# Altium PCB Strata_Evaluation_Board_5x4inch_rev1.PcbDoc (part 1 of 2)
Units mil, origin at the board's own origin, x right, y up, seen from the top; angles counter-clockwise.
Board outline 5000 x 4000 mil, 2 copper layers (Top Layer, Bottom Layer); 99 components, 40 nets, 363 pads, 393 vias.
Unrouted connection lines stored in the file: 5.
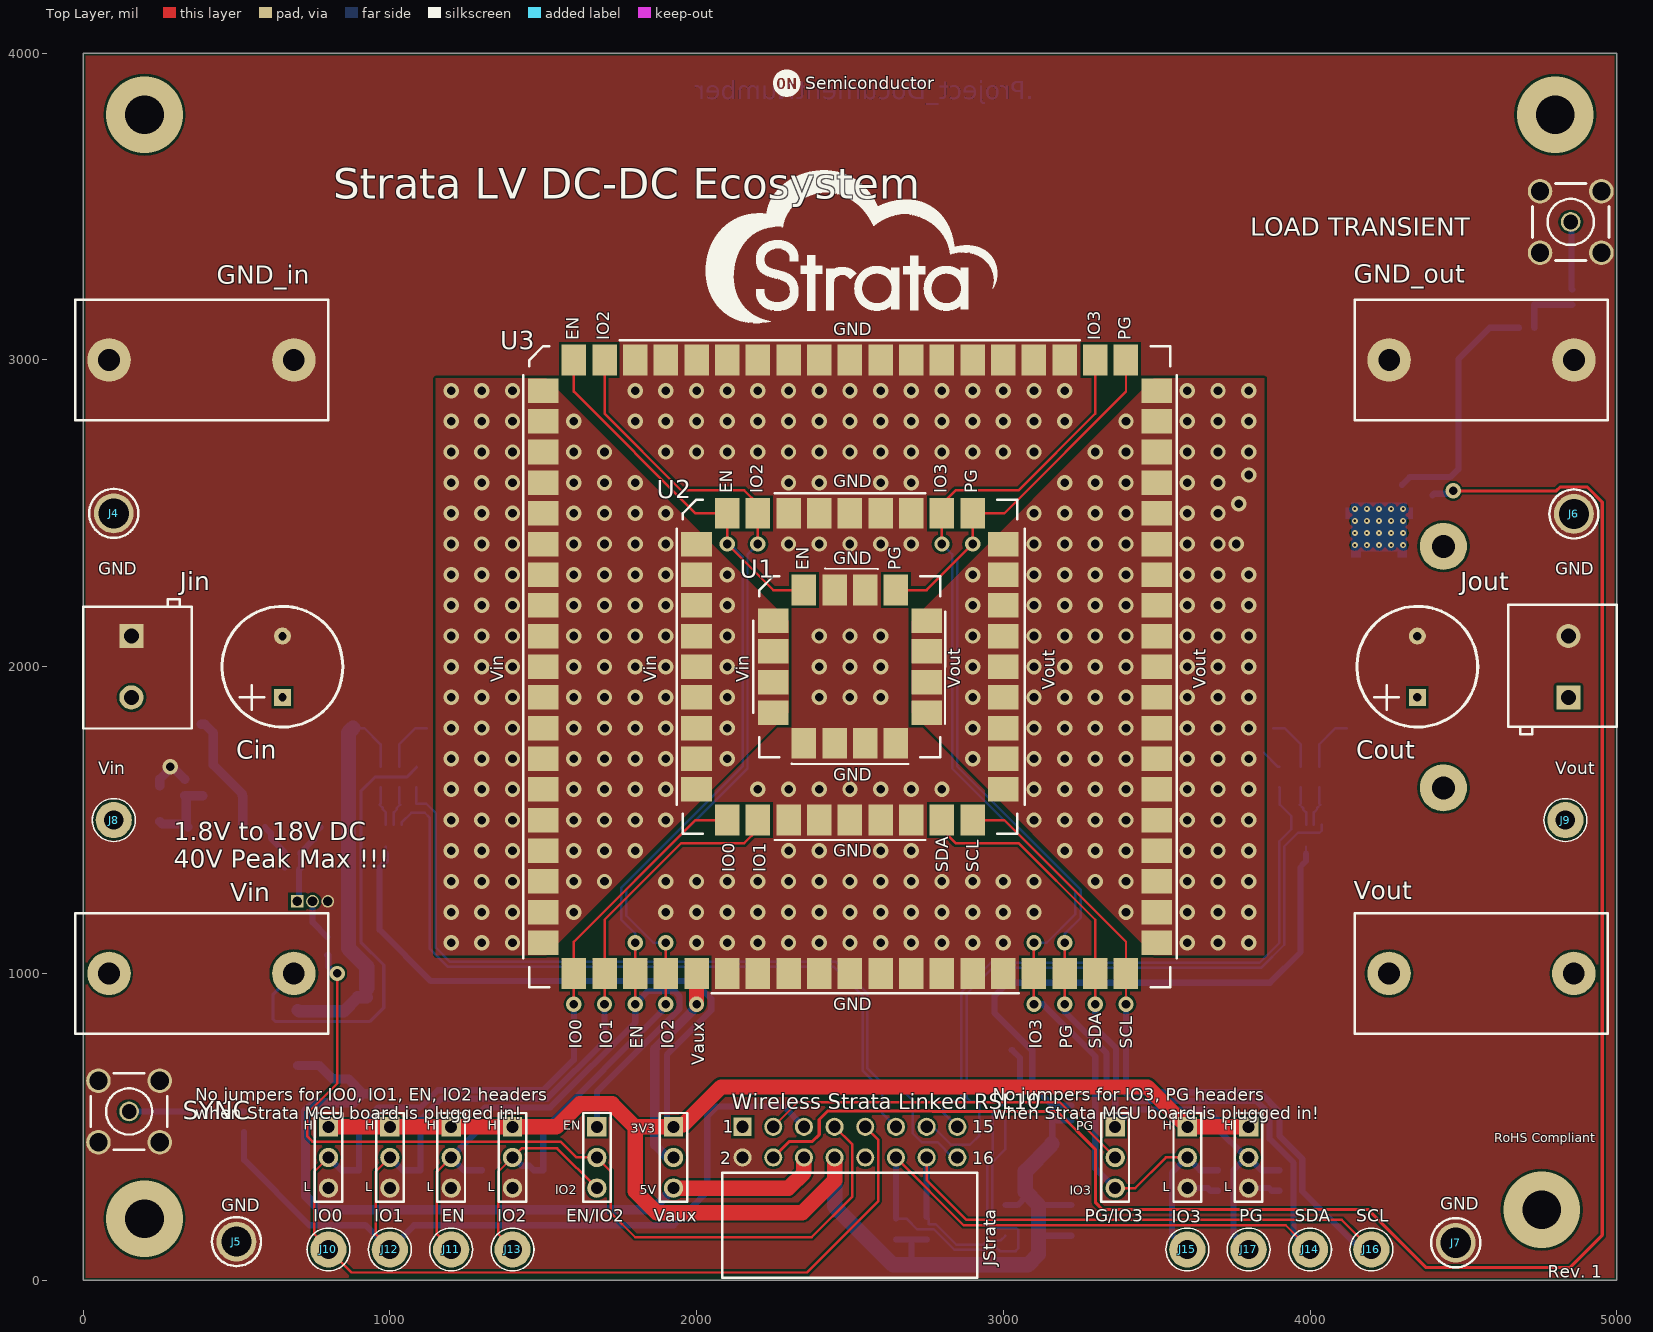
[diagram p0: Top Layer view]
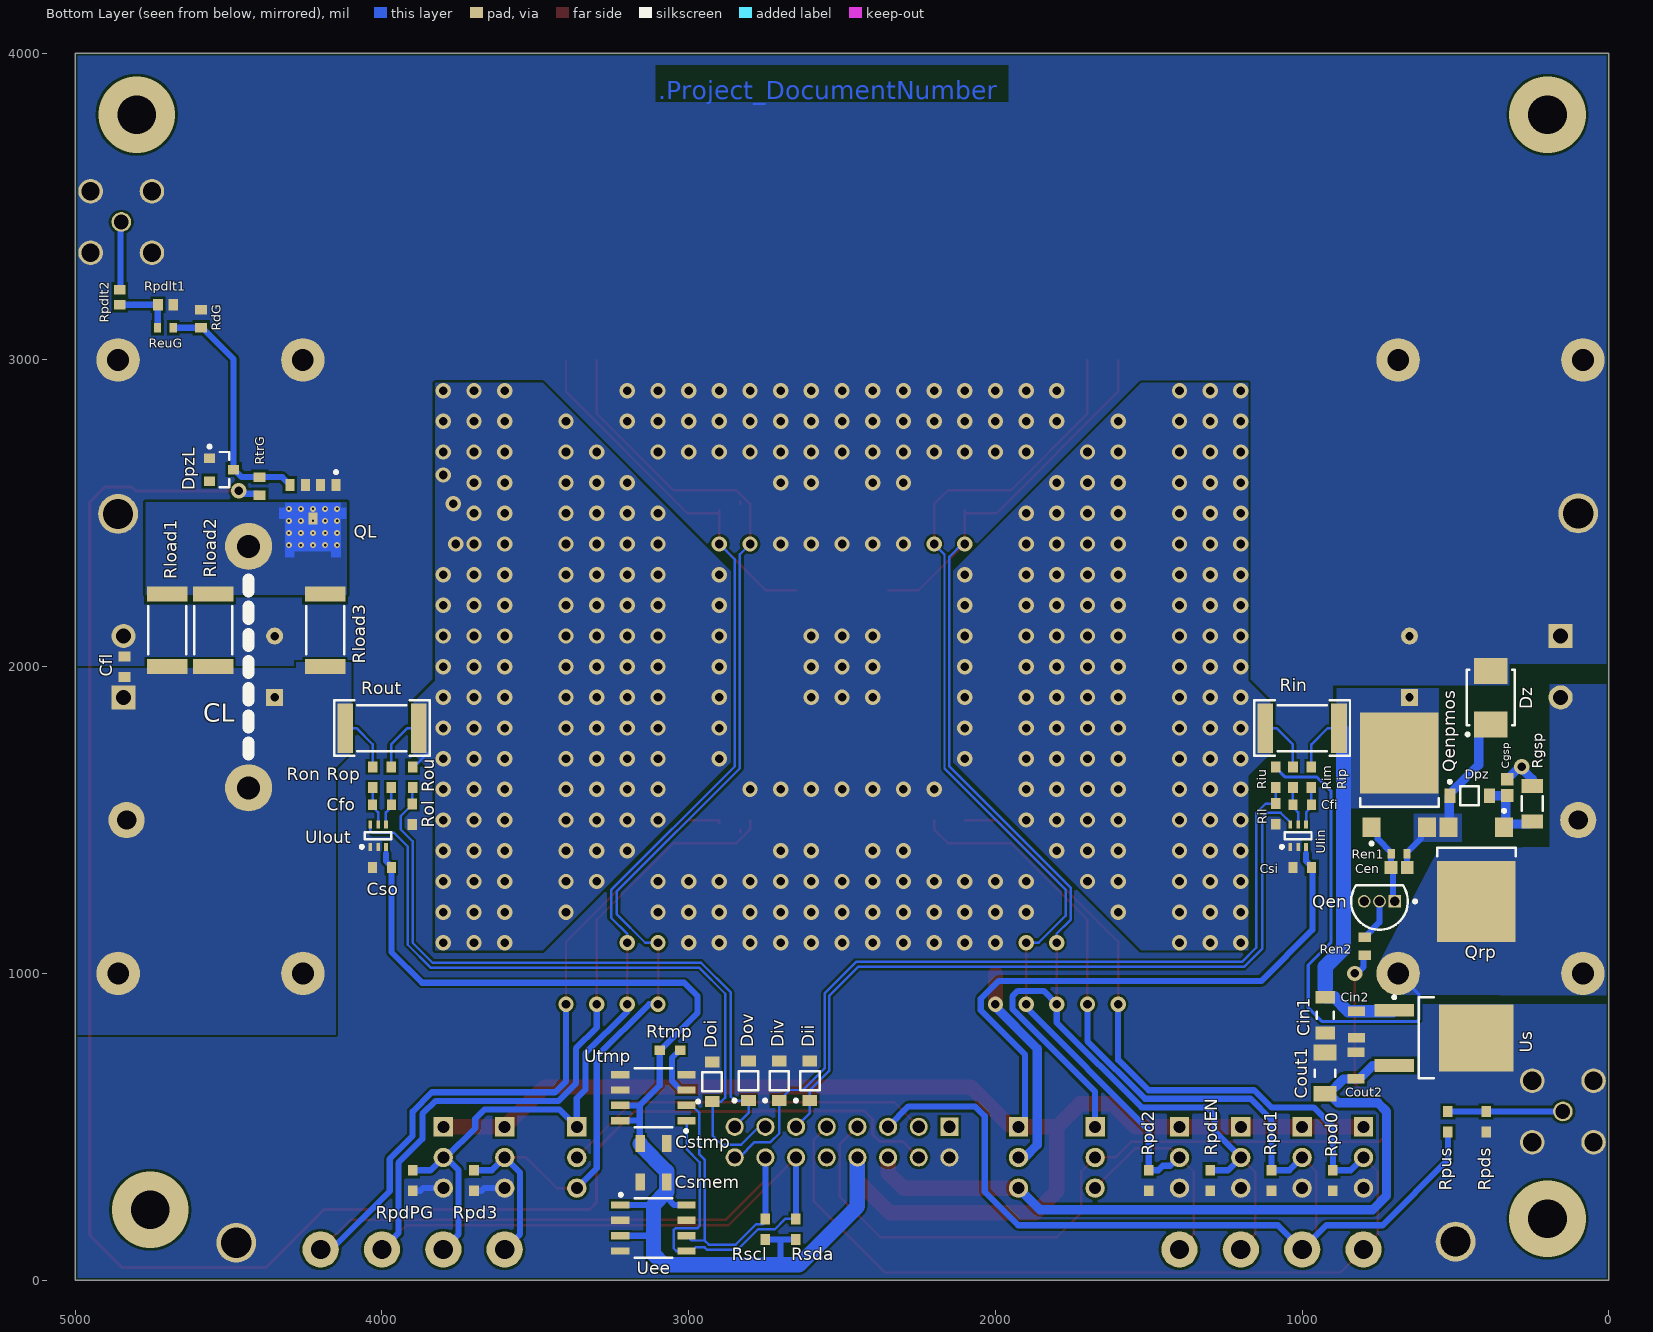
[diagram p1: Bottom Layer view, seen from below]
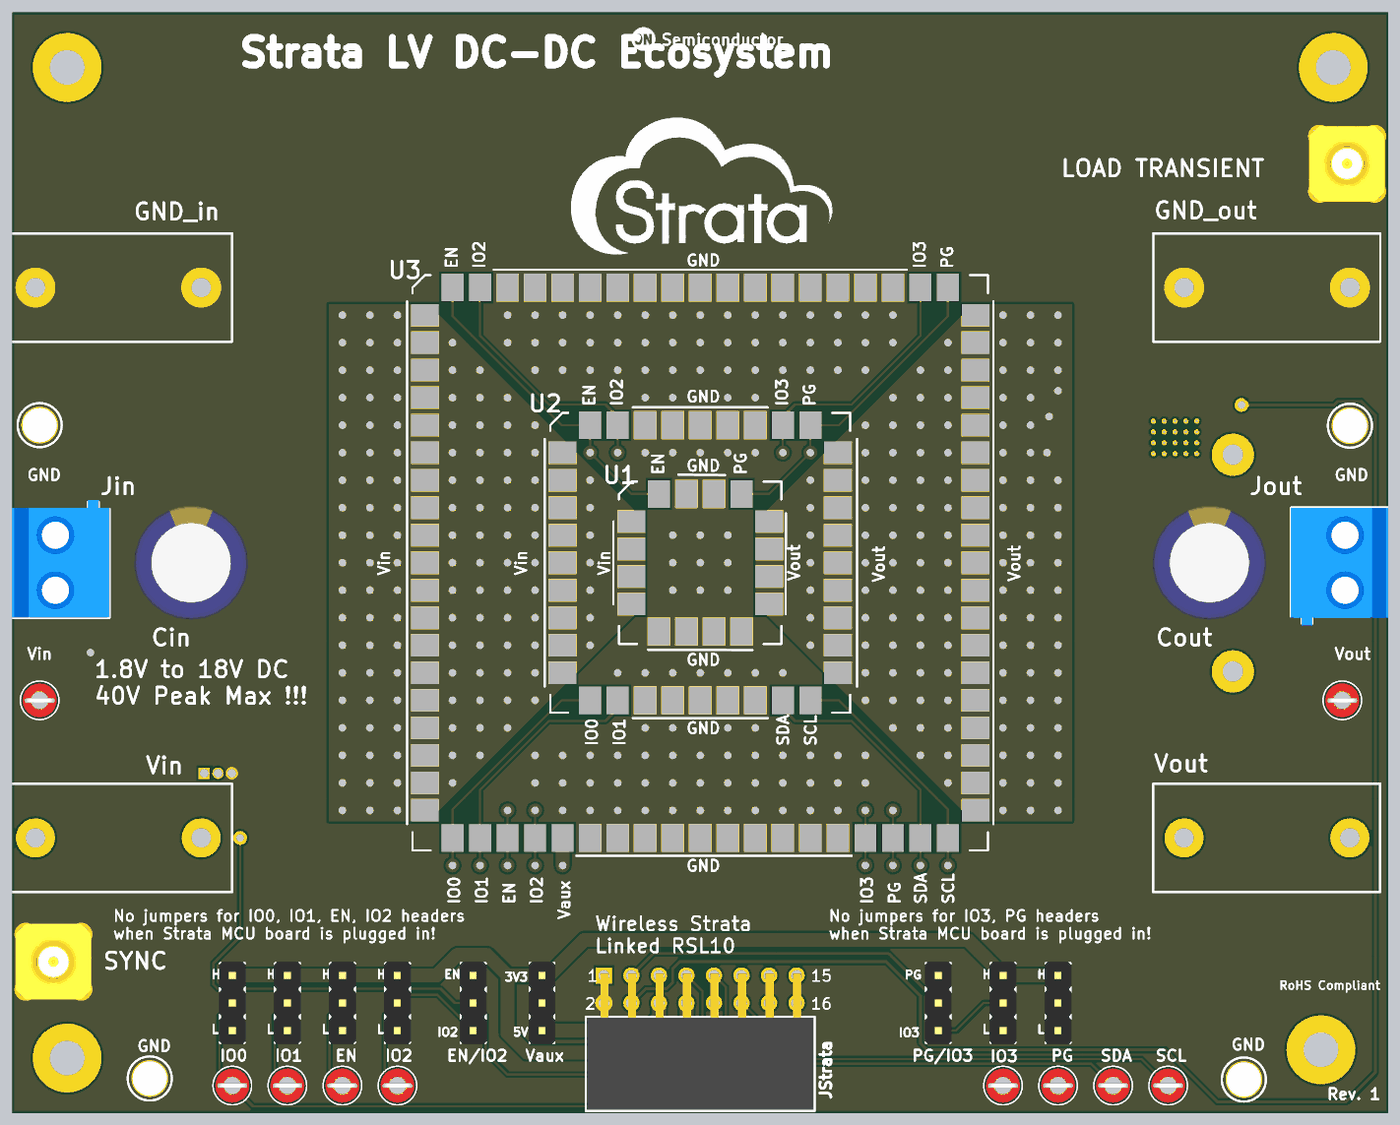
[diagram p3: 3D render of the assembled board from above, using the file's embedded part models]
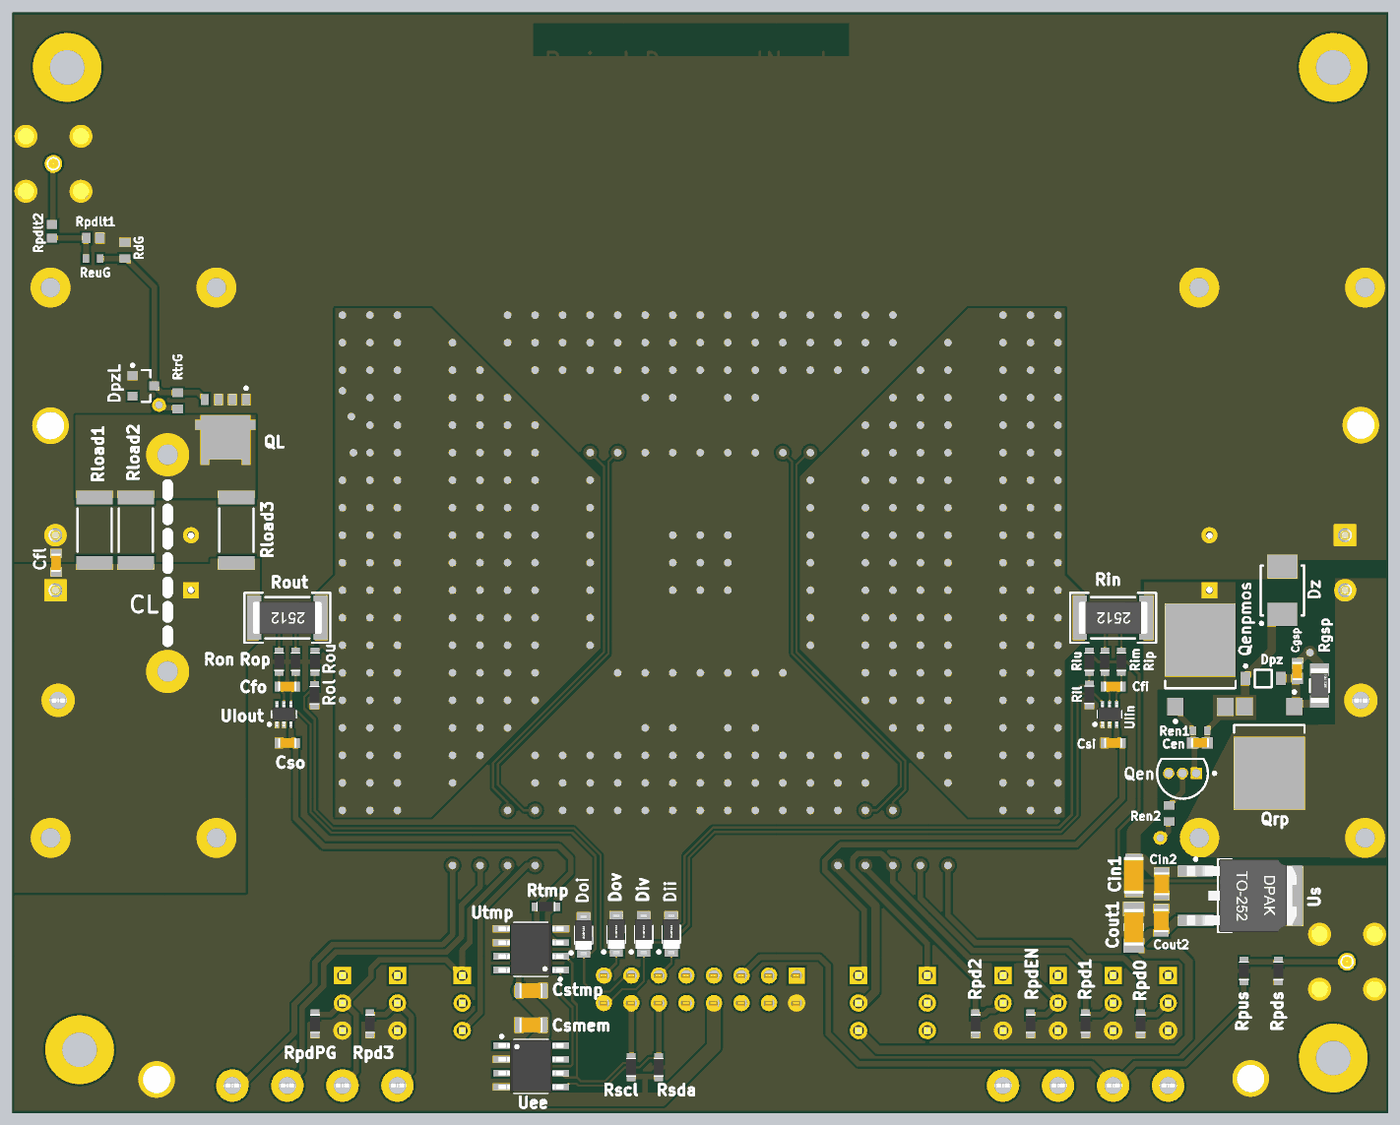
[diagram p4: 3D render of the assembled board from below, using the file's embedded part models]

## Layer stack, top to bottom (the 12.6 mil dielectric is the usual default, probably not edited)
Top Solder: solder mask 0.4, Solder Resist, Dk 3.5
Top Layer: signal copper 1.4
Dielectric 1: dielectric 12.6, FR-4, Dk 4.8
Bottom Layer: signal copper 1.4
Bottom Solder: solder mask 0.4, Solder Resist, Dk 3.5

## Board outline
0,0 5000,0 5000,4000 0,4000

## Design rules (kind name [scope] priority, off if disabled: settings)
BoardOutlineClearance BoardOutlineClearance_TOP [OnLayer('Top Layer')] p1: gap=8 ignorepadtopadclearanceinfootprint=FALSE
BoardOutlineClearance BoardOutlineClearance_BOTTOM [OnLayer('Bottom Layer')] p2: gap=8 ignorepadtopadclearanceinfootprint=FALSE
Clearance [All] p1: gap=8 ignorepadtopadclearanceinfootprint=FALSE
ComponentClearance [All] p1: gap=-10000 collisioncheckmode=3 verticalgap=10 showdistances=FALSE
DiffPairsRouting [All] p1: maxlimit=10 minlimit=6 mostfreqgap=10 toplayer_minwidth=6 toplayer_maxwidth=20 toplayer_prefwidth=10 bottomlayer_minwidth=6 bottomlayer_maxwidth=20 bottomlayer_prefwidth=10 maxuncoupledlength=500
HoleSize [All] p1: absolutevalues=TRUE maxlimit=400 minlimit=8 maxpercent=80.000 minpercent=20.000
MinimumSolderMaskSliver [All] p1: minsoldermaskwidth=1.57
PlaneClearance [All] p1: clearance=6
PolygonConnect Polygon_Direct [All] p1: connectstyle=Direct reliefconductorwidth=10 reliefentries=4 polygonreliefangle="90 Angle" airgapwidth=10
PolygonConnect PolygonConnect_85 [All vs IsNamedPolygon('GND_L01_P2321')] p2: connectstyle=Direct reliefconductorwidth=10 reliefentries=4 polygonreliefangle="90 Angle" airgapwidth=10
PolygonConnect PolygonConnect_84 [All vs IsNamedPolygon('GND_L03_P1821')] p3: connectstyle=Direct reliefconductorwidth=10 reliefentries=4 polygonreliefangle="90 Angle" airgapwidth=10
PolygonConnect PolygonConnect_83 [All vs IsNamedPolygon('VOUTMP_L05_P1813')] p4: connectstyle=Direct reliefconductorwidth=10 reliefentries=4 polygonreliefangle="90 Angle" airgapwidth=10
PolygonConnect PolygonConnect_82 [All vs IsNamedPolygon('VOUTMP_L04_P1815')] p5: connectstyle=Direct reliefconductorwidth=10 reliefentries=4 polygonreliefangle="90 Angle" airgapwidth=10
PolygonConnect PolygonConnect_81 [All vs IsNamedPolygon('GND_L06_P2169')] p6: connectstyle=Direct reliefconductorwidth=10 reliefentries=4 polygonreliefangle="90 Angle" airgapwidth=10
PolygonConnect PolygonConnect_80 [All vs IsNamedPolygon('GND_L06_P2377')] p7: connectstyle=Direct reliefconductorwidth=10 reliefentries=4 polygonreliefangle="90 Angle" airgapwidth=10
PolygonConnect PolygonConnect_79 [All vs IsNamedPolygon('VOUTMP_L04_P1803')] p8: connectstyle=Direct reliefconductorwidth=10 reliefentries=4 polygonreliefangle="90 Angle" airgapwidth=10
PolygonConnect PolygonConnect_78 [All vs IsNamedPolygon('VCC_DUT_L04_P1801')] p9: connectstyle=Direct reliefconductorwidth=10 reliefentries=4 polygonreliefangle="90 Angle" airgapwidth=10
PolygonConnect PolygonConnect_77 [All vs IsNamedPolygon('GND_L06_P1795')] p10: thpad.connectstyle=Relief thpad.reliefconductorwidth=10 thpad.reliefentries=4 thpad.polygonreliefangle="90 Angle" thpad.airgapwidth=10 smdpad.connectstyle=Direct smdpad.reliefconductorwidth=10 smdpad.reliefentries=4 smdpad.polygonreliefangle="90 Angle" smdpad.airgapwidth=10 via.connectstyle=Direct via.reliefconductorwidth=10 via.reliefentries=4 via.polygonreliefangle="90 Angle" via.airgapwidth=10
PolygonConnect PolygonConnect_76 [All vs IsNamedPolygon('GND_L02_P1793')] p11: connectstyle=Direct reliefconductorwidth=10 reliefentries=4 polygonreliefangle="90 Angle" airgapwidth=10
PolygonConnect PolygonConnect_75 [All vs IsNamedPolygon('GND_L03_P1791')] p12: thpad.connectstyle=Relief thpad.reliefconductorwidth=10 thpad.reliefentries=4 thpad.polygonreliefangle="90 Angle" thpad.airgapwidth=10 smdpad.connectstyle=Direct smdpad.reliefconductorwidth=10 smdpad.reliefentries=4 smdpad.polygonreliefangle="90 Angle" smdpad.airgapwidth=10 via.connectstyle=Direct via.reliefconductorwidth=10 via.reliefentries=4 via.polygonreliefangle="90 Angle" via.airgapwidth=10
PolygonConnect PolygonConnect_74 [All vs IsNamedPolygon('NETQLMPB_5_L06_P1787')] p13: thpad.connectstyle=Relief thpad.reliefconductorwidth=10 thpad.reliefentries=4 thpad.polygonreliefangle="90 Angle" thpad.airgapwidth=10 smdpad.connectstyle=Direct smdpad.reliefconductorwidth=10 smdpad.reliefentries=4 smdpad.polygonreliefangle="90 Angle" smdpad.airgapwidth=10 via.connectstyle=Direct via.reliefconductorwidth=10 via.reliefentries=4 via.polygonreliefangle="90 Angle" via.airgapwidth=10
PolygonConnect PolygonConnect_73 [All vs IsNamedPolygon('NETQLMPA_5_L06_P1789')] p14: thpad.connectstyle=Relief thpad.reliefconductorwidth=10 thpad.reliefentries=4 thpad.polygonreliefangle="90 Angle" thpad.airgapwidth=10 smdpad.connectstyle=Direct smdpad.reliefconductorwidth=10 smdpad.reliefentries=4 smdpad.polygonreliefangle="90 Angle" smdpad.airgapwidth=10 via.connectstyle=Direct via.reliefconductorwidth=10 via.reliefentries=4 via.polygonreliefangle="90 Angle" via.airgapwidth=10
PolygonConnect PolygonConnect_72 [All vs IsNamedPolygon('NETQLMPC_5_L06_P1738')] p15: thpad.connectstyle=Relief thpad.reliefconductorwidth=10 thpad.reliefentries=4 thpad.polygonreliefangle="90 Angle" thpad.airgapwidth=10 smdpad.connectstyle=Direct smdpad.reliefconductorwidth=10 smdpad.reliefentries=4 smdpad.polygonreliefangle="90 Angle" smdpad.airgapwidth=10 via.connectstyle=Direct via.reliefconductorwidth=10 via.reliefentries=4 via.polygonreliefangle="90 Angle" via.airgapwidth=10
PolygonConnect PolygonConnect_71 [All vs IsNamedPolygon('NETQL12_5_L06_P1740')] p16: thpad.connectstyle=Relief thpad.reliefconductorwidth=10 thpad.reliefentries=4 thpad.polygonreliefangle="90 Angle" thpad.airgapwidth=10 smdpad.connectstyle=Direct smdpad.reliefconductorwidth=10 smdpad.reliefentries=4 smdpad.polygonreliefangle="90 Angle" smdpad.airgapwidth=10 via.connectstyle=Direct via.reliefconductorwidth=10 via.reliefentries=4 via.polygonreliefangle="90 Angle" via.airgapwidth=10
PolygonConnect PolygonConnect_70 [All vs IsNamedPolygon('NETQL12_5_L06_P1740')] p17: thpad.connectstyle=Relief thpad.reliefconductorwidth=10 thpad.reliefentries=4 thpad.polygonreliefangle="90 Angle" thpad.airgapwidth=10 smdpad.connectstyle=Direct smdpad.reliefconductorwidth=10 smdpad.reliefentries=4 smdpad.polygonreliefangle="90 Angle" smdpad.airgapwidth=10 via.connectstyle=Direct via.reliefconductorwidth=10 via.reliefentries=4 via.polygonreliefangle="90 Angle" via.airgapwidth=10
PolygonConnect PolygonConnect_69 [All vs IsNamedPolygon('NETQLMPD_5_L06_P1736')] p18: thpad.connectstyle=Relief thpad.reliefconductorwidth=10 thpad.reliefentries=4 thpad.polygonreliefangle="90 Angle" thpad.airgapwidth=10 smdpad.connectstyle=Direct smdpad.reliefconductorwidth=10 smdpad.reliefentries=4 smdpad.polygonreliefangle="90 Angle" smdpad.airgapwidth=10 via.connectstyle=Direct via.reliefconductorwidth=10 via.reliefentries=4 via.polygonreliefangle="90 Angle" via.airgapwidth=10
PolygonConnect PolygonConnect_68 [All vs IsNamedPolygon('NETQLMPA_5_L06_P1722')] p19: thpad.connectstyle=Relief thpad.reliefconductorwidth=10 thpad.reliefentries=4 thpad.polygonreliefangle="90 Angle" thpad.airgapwidth=10 smdpad.connectstyle=Direct smdpad.reliefconductorwidth=10 smdpad.reliefentries=4 smdpad.polygonreliefangle="90 Angle" smdpad.airgapwidth=10 via.connectstyle=Direct via.reliefconductorwidth=10 via.reliefentries=4 via.polygonreliefangle="90 Angle" via.airgapwidth=10
PolygonConnect PolygonConnect_67 [All vs IsNamedPolygon('GND_L03_P1716')] p20: connectstyle=Direct reliefconductorwidth=10 reliefentries=4 polygonreliefangle="90 Angle" airgapwidth=10
PolygonConnect PolygonConnect_66 [All vs IsNamedPolygon('GND_L03_P1716')] p21: thpad.connectstyle=Relief thpad.reliefconductorwidth=10 thpad.reliefentries=4 thpad.polygonreliefangle="90 Angle" thpad.airgapwidth=10 smdpad.connectstyle=Relief smdpad.reliefconductorwidth=10 smdpad.reliefentries=4 smdpad.polygonreliefangle="90 Angle" smdpad.airgapwidth=10 via.connectstyle=Direct via.reliefconductorwidth=10 via.reliefentries=4 via.polygonreliefangle="90 Angle" via.airgapwidth=10
PolygonConnect PolygonConnect_65 [All vs IsNamedPolygon('GND_L03_P1716')] p22: thpad.connectstyle=Direct thpad.reliefconductorwidth=10 thpad.reliefentries=4 thpad.polygonreliefangle="90 Angle" thpad.airgapwidth=10 smdpad.connectstyle=Relief smdpad.reliefconductorwidth=10 smdpad.reliefentries=4 smdpad.polygonreliefangle="90 Angle" smdpad.airgapwidth=10 via.connectstyle=Relief via.reliefconductorwidth=10 via.reliefentries=4 via.polygonreliefangle="90 Angle" via.airgapwidth=10
PolygonConnect PolygonConnect_64 [All vs IsNamedPolygon('GND_L03_P1716')] p23: connectstyle=Relief reliefconductorwidth=10 reliefentries=4 polygonreliefangle="90 Angle" airgapwidth=10
PolygonConnect PolygonConnect_63 [All vs IsNamedPolygon('GND_L04_P1728')] p24: connectstyle=Direct reliefconductorwidth=10 reliefentries=4 polygonreliefangle="90 Angle" airgapwidth=10
PolygonConnect PolygonConnect_62 [All vs IsNamedPolygon('G11_L04_P1730')] p25: thpad.connectstyle=Relief thpad.reliefconductorwidth=10 thpad.reliefentries=4 thpad.polygonreliefangle="90 Angle" thpad.airgapwidth=10 smdpad.connectstyle=Direct smdpad.reliefconductorwidth=10 smdpad.reliefentries=4 smdpad.polygonreliefangle="90 Angle" smdpad.airgapwidth=10 via.connectstyle=Direct via.reliefconductorwidth=10 via.reliefentries=4 via.polygonreliefangle="90 Angle" via.airgapwidth=10
PolygonConnect PolygonConnect_61 [All vs IsNamedPolygon('NETQL11_5_L04_P1732')] p26: thpad.connectstyle=Relief thpad.reliefconductorwidth=10 thpad.reliefentries=4 thpad.polygonreliefangle="90 Angle" thpad.airgapwidth=10 smdpad.connectstyle=Direct smdpad.reliefconductorwidth=10 smdpad.reliefentries=4 smdpad.polygonreliefangle="90 Angle" smdpad.airgapwidth=10 via.connectstyle=Direct via.reliefconductorwidth=10 via.reliefentries=4 via.polygonreliefangle="90 Angle" via.airgapwidth=10
PolygonConnect PolygonConnect_60 [All vs IsNamedPolygon('GND_L04_P1718')] p27: connectstyle=Direct reliefconductorwidth=10 reliefentries=4 polygonreliefangle="90 Angle" airgapwidth=10
PolygonConnect PolygonConnect_59 [All vs IsNamedPolygon('G12_L04_P1716')] p28: thpad.connectstyle=Relief thpad.reliefconductorwidth=10 thpad.reliefentries=4 thpad.polygonreliefangle="90 Angle" thpad.airgapwidth=10 smdpad.connectstyle=Direct smdpad.reliefconductorwidth=10 smdpad.reliefentries=4 smdpad.polygonreliefangle="90 Angle" smdpad.airgapwidth=10 via.connectstyle=Direct via.reliefconductorwidth=10 via.reliefentries=4 via.polygonreliefangle="90 Angle" via.airgapwidth=10
PolygonConnect PolygonConnect_58 [All vs IsNamedPolygon('NETQL12_5_L04_P1712')] p29: connectstyle=Direct reliefconductorwidth=10 reliefentries=4 polygonreliefangle="90 Angle" airgapwidth=10
PolygonConnect PolygonConnect_57 [All vs IsNamedPolygon('VOUT111_L01_P1710')] p30: thpad.connectstyle=Direct thpad.reliefconductorwidth=10 thpad.reliefentries=4 thpad.polygonreliefangle="90 Angle" thpad.airgapwidth=10 smdpad.connectstyle=Relief smdpad.reliefconductorwidth=10 smdpad.reliefentries=4 smdpad.polygonreliefangle="90 Angle" smdpad.airgapwidth=10 via.connectstyle=Direct via.reliefconductorwidth=10 via.reliefentries=4 via.polygonreliefangle="90 Angle" via.airgapwidth=10
PolygonConnect PolygonConnect_56 [All vs IsNamedPolygon('VCC_DUT_L06_P1734')] p31: connectstyle=Direct reliefconductorwidth=10 reliefentries=4 polygonreliefangle="90 Angle" airgapwidth=10
PolygonConnect PolygonConnect_55 [All vs IsNamedPolygon('NETC5_1_L01_P1688')] p32: thpad.connectstyle=Relief thpad.reliefconductorwidth=10 thpad.reliefentries=4 thpad.polygonreliefangle="90 Angle" thpad.airgapwidth=10 smdpad.connectstyle=Direct smdpad.reliefconductorwidth=10 smdpad.reliefentries=4 smdpad.polygonreliefangle="90 Angle" smdpad.airgapwidth=10 via.connectstyle=Direct via.reliefconductorwidth=10 via.reliefentries=4 via.polygonreliefangle="90 Angle" via.airgapwidth=10
PolygonConnect PolygonConnect_54 [All vs IsNamedPolygon('GND_L01_P1700')] p33: thpad.connectstyle=Relief thpad.reliefconductorwidth=10 thpad.reliefentries=4 thpad.polygonreliefangle="90 Angle" thpad.airgapwidth=10 smdpad.connectstyle=Direct smdpad.reliefconductorwidth=10 smdpad.reliefentries=4 smdpad.polygonreliefangle="90 Angle" smdpad.airgapwidth=10 via.connectstyle=Direct via.reliefconductorwidth=10 via.reliefentries=4 via.polygonreliefangle="90 Angle" via.airgapwidth=10
PolygonConnect PolygonConnect_53 [All vs IsNamedPolygon('GND_L01_P1608')] p34: thpad.connectstyle=Relief thpad.reliefconductorwidth=10 thpad.reliefentries=4 thpad.polygonreliefangle="90 Angle" thpad.airgapwidth=10 smdpad.connectstyle=Direct smdpad.reliefconductorwidth=10 smdpad.reliefentries=4 smdpad.polygonreliefangle="90 Angle" smdpad.airgapwidth=10 via.connectstyle=Direct via.reliefconductorwidth=10 via.reliefentries=4 via.polygonreliefangle="90 Angle" via.airgapwidth=10
PolygonConnect PolygonConnect_52 [All vs IsNamedPolygon('VREF_L01_P1696')] p35: connectstyle=Direct reliefconductorwidth=10 reliefentries=4 polygonreliefangle="90 Angle" airgapwidth=10
PolygonConnect PolygonConnect_51 [All vs IsNamedPolygon('VREF_L01_P1696')] p36: thpad.connectstyle=Relief thpad.reliefconductorwidth=10 thpad.reliefentries=4 thpad.polygonreliefangle="90 Angle" thpad.airgapwidth=10 smdpad.connectstyle=Direct smdpad.reliefconductorwidth=10 smdpad.reliefentries=4 smdpad.polygonreliefangle="90 Angle" smdpad.airgapwidth=10 via.connectstyle=Direct via.reliefconductorwidth=10 via.reliefentries=4 via.polygonreliefangle="90 Angle" via.airgapwidth=10
PolygonConnect PolygonConnect_50 [All vs IsNamedPolygon('NETC2_1_L01_P1698')] p37: thpad.connectstyle=Relief thpad.reliefconductorwidth=10 thpad.reliefentries=4 thpad.polygonreliefangle="90 Angle" thpad.airgapwidth=10 smdpad.connectstyle=Direct smdpad.reliefconductorwidth=10 smdpad.reliefentries=4 smdpad.polygonreliefangle="90 Angle" smdpad.airgapwidth=10 via.connectstyle=Direct via.reliefconductorwidth=10 via.reliefentries=4 via.polygonreliefangle="90 Angle" via.airgapwidth=10
PolygonConnect PolygonConnect_49 [All vs IsNamedPolygon('NETC1_1_L01_P1694')] p38: thpad.connectstyle=Relief thpad.reliefconductorwidth=10 thpad.reliefentries=4 thpad.polygonreliefangle="90 Angle" thpad.airgapwidth=10 smdpad.connectstyle=Direct smdpad.reliefconductorwidth=10 smdpad.reliefentries=4 smdpad.polygonreliefangle="90 Angle" smdpad.airgapwidth=10 via.connectstyle=Direct via.reliefconductorwidth=10 via.reliefentries=4 via.polygonreliefangle="90 Angle" via.airgapwidth=10
PolygonConnect PolygonConnect_48 [All vs IsNamedPolygon('VID_BUFF_L01_P1690')] p39: thpad.connectstyle=Relief thpad.reliefconductorwidth=10 thpad.reliefentries=4 thpad.polygonreliefangle="90 Angle" thpad.airgapwidth=10 smdpad.connectstyle=Direct smdpad.reliefconductorwidth=10 smdpad.reliefentries=4 smdpad.polygonreliefangle="90 Angle" smdpad.airgapwidth=10 via.connectstyle=Direct via.reliefconductorwidth=10 via.reliefentries=4 via.polygonreliefangle="90 Angle" via.airgapwidth=10
PolygonConnect PolygonConnect_47 [All vs IsNamedPolygon('NETCVCC_1_L01_P1690')] p40: thpad.connectstyle=Relief thpad.reliefconductorwidth=10 thpad.reliefentries=4 thpad.polygonreliefangle="90 Angle" thpad.airgapwidth=10 smdpad.connectstyle=Direct smdpad.reliefconductorwidth=10 smdpad.reliefentries=4 smdpad.polygonreliefangle="90 Angle" smdpad.airgapwidth=10 via.connectstyle=Direct via.reliefconductorwidth=10 via.reliefentries=4 via.polygonreliefangle="90 Angle" via.airgapwidth=10
PolygonConnect PolygonConnect_46 [All vs IsNamedPolygon('REFIN_L01_P1686')] p41: thpad.connectstyle=Relief thpad.reliefconductorwidth=10 thpad.reliefentries=4 thpad.polygonreliefangle="90 Angle" thpad.airgapwidth=10 smdpad.connectstyle=Direct smdpad.reliefconductorwidth=10 smdpad.reliefentries=4 smdpad.polygonreliefangle="90 Angle" smdpad.airgapwidth=10 via.connectstyle=Direct via.reliefconductorwidth=10 via.reliefentries=4 via.polygonreliefangle="90 Angle" via.airgapwidth=10
PolygonConnect PolygonConnect_45 [All vs IsNamedPolygon('CSREF_L06_P1706')] p42: thpad.connectstyle=Relief thpad.reliefconductorwidth=10 thpad.reliefentries=4 thpad.polygonreliefangle="90 Angle" thpad.airgapwidth=10 smdpad.connectstyle=Direct smdpad.reliefconductorwidth=10 smdpad.reliefentries=4 smdpad.polygonreliefangle="90 Angle" smdpad.airgapwidth=10 via.connectstyle=Direct via.reliefconductorwidth=10 via.reliefentries=4 via.polygonreliefangle="90 Angle" via.airgapwidth=10
PolygonConnect PolygonConnect_44 [All vs IsNamedPolygon('GND_L01_P1612')] p43: thpad.connectstyle=Relief thpad.reliefconductorwidth=10 thpad.reliefentries=4 thpad.polygonreliefangle="90 Angle" thpad.airgapwidth=10 smdpad.connectstyle=Direct smdpad.reliefconductorwidth=10 smdpad.reliefentries=4 smdpad.polygonreliefangle="90 Angle" smdpad.airgapwidth=10 via.connectstyle=Direct via.reliefconductorwidth=10 via.reliefentries=4 via.polygonreliefangle="90 Angle" via.airgapwidth=10
PolygonConnect PolygonConnect_43 [All vs IsNamedPolygon('CSREF_L01_P1682')] p44: thpad.connectstyle=Relief thpad.reliefconductorwidth=10 thpad.reliefentries=4 thpad.polygonreliefangle="90 Angle" thpad.airgapwidth=10 smdpad.connectstyle=Direct smdpad.reliefconductorwidth=10 smdpad.reliefentries=4 smdpad.polygonreliefangle="90 Angle" smdpad.airgapwidth=10 via.connectstyle=Direct via.reliefconductorwidth=10 via.reliefentries=4 via.polygonreliefangle="90 Angle" via.airgapwidth=10
PolygonConnect PolygonConnect_42 [All vs IsNamedPolygon('VIN1_L06_P222')] p45: thpad.connectstyle=Relief thpad.reliefconductorwidth=10 thpad.reliefentries=4 thpad.polygonreliefangle="90 Angle" thpad.airgapwidth=10 smdpad.connectstyle=Direct smdpad.reliefconductorwidth=10 smdpad.reliefentries=4 smdpad.polygonreliefangle="90 Angle" smdpad.airgapwidth=10 via.connectstyle=Direct via.reliefconductorwidth=10 via.reliefentries=4 via.polygonreliefangle="90 Angle" via.airgapwidth=10
PolygonConnect PolygonConnect_41 [All vs IsNamedPolygon('VIN1_L06_P1450')] p46: thpad.connectstyle=Relief thpad.reliefconductorwidth=10 thpad.reliefentries=4 thpad.polygonreliefangle="90 Angle" thpad.airgapwidth=10 smdpad.connectstyle=Direct smdpad.reliefconductorwidth=10 smdpad.reliefentries=4 smdpad.polygonreliefangle="90 Angle" smdpad.airgapwidth=10 via.connectstyle=Direct via.reliefconductorwidth=10 via.reliefentries=4 via.polygonreliefangle="90 Angle" via.airgapwidth=10
PolygonConnect PolygonConnect_40 [All vs IsNamedPolygon('VIN1_L06_P1450')] p47: thpad.connectstyle=Relief thpad.reliefconductorwidth=10 thpad.reliefentries=4 thpad.polygonreliefangle="90 Angle" thpad.airgapwidth=10 smdpad.connectstyle=Direct smdpad.reliefconductorwidth=10 smdpad.reliefentries=4 smdpad.polygonreliefangle="90 Angle" smdpad.airgapwidth=10 via.connectstyle=Direct via.reliefconductorwidth=10 via.reliefentries=4 via.polygonreliefangle="90 Angle" via.airgapwidth=10
PolygonConnect PolygonConnect_39 [All vs IsNamedPolygon('VIN1_L06_P1530')] p48: thpad.connectstyle=Relief thpad.reliefconductorwidth=10 thpad.reliefentries=4 thpad.polygonreliefangle="90 Angle" thpad.airgapwidth=10 smdpad.connectstyle=Direct smdpad.reliefconductorwidth=10 smdpad.reliefentries=4 smdpad.polygonreliefangle="90 Angle" smdpad.airgapwidth=10 via.connectstyle=Direct via.reliefconductorwidth=10 via.reliefentries=4 via.polygonreliefangle="90 Angle" via.airgapwidth=10
PolygonConnect PolygonConnect_38 [All vs IsNamedPolygon('VIN1_L06_P1562')] p49: thpad.connectstyle=Relief thpad.reliefconductorwidth=10 thpad.reliefentries=4 thpad.polygonreliefangle="90 Angle" thpad.airgapwidth=10 smdpad.connectstyle=Direct smdpad.reliefconductorwidth=10 smdpad.reliefentries=4 smdpad.polygonreliefangle="90 Angle" smdpad.airgapwidth=10 via.connectstyle=Direct via.reliefconductorwidth=10 via.reliefentries=4 via.polygonreliefangle="90 Angle" via.airgapwidth=10
PolygonConnect PolygonConnect_37 [All vs IsNamedPolygon('VIN1_L06_P1530')] p50: thpad.connectstyle=Relief thpad.reliefconductorwidth=10 thpad.reliefentries=4 thpad.polygonreliefangle="90 Angle" thpad.airgapwidth=10 smdpad.connectstyle=Direct smdpad.reliefconductorwidth=10 smdpad.reliefentries=4 smdpad.polygonreliefangle="90 Angle" smdpad.airgapwidth=10 via.connectstyle=Direct via.reliefconductorwidth=10 via.reliefentries=4 via.polygonreliefangle="90 Angle" via.airgapwidth=10
PolygonConnect PolygonConnect_36 [All vs IsNamedPolygon('VIN1_L06_P1530')] p51: thpad.connectstyle=Relief thpad.reliefconductorwidth=10 thpad.reliefentries=4 thpad.polygonreliefangle="90 Angle" thpad.airgapwidth=10 smdpad.connectstyle=Direct smdpad.reliefconductorwidth=10 smdpad.reliefentries=4 smdpad.polygonreliefangle="90 Angle" smdpad.airgapwidth=10 via.connectstyle=Direct via.reliefconductorwidth=10 via.reliefentries=4 via.polygonreliefangle="90 Angle" via.airgapwidth=10
PolygonConnect PolygonConnect_35 [All vs IsNamedPolygon('VIN1_L06_P1636')] p52: thpad.connectstyle=Relief thpad.reliefconductorwidth=10 thpad.reliefentries=4 thpad.polygonreliefangle="90 Angle" thpad.airgapwidth=10 smdpad.connectstyle=Direct smdpad.reliefconductorwidth=10 smdpad.reliefentries=4 smdpad.polygonreliefangle="90 Angle" smdpad.airgapwidth=10 via.connectstyle=Direct via.reliefconductorwidth=10 via.reliefentries=4 via.polygonreliefangle="90 Angle" via.airgapwidth=10
PolygonConnect PolygonConnect_34 [All vs IsNamedPolygon('GND_L01_P1614')] p53: thpad.connectstyle=Relief thpad.reliefconductorwidth=10 thpad.reliefentries=4 thpad.polygonreliefangle="90 Angle" thpad.airgapwidth=10 smdpad.connectstyle=Direct smdpad.reliefconductorwidth=10 smdpad.reliefentries=4 smdpad.polygonreliefangle="90 Angle" smdpad.airgapwidth=10 via.connectstyle=Direct via.reliefconductorwidth=10 via.reliefentries=4 via.polygonreliefangle="90 Angle" via.airgapwidth=10
PolygonConnect PolygonConnect_33 [All vs IsNamedPolygon('CSSUM_L01_P1600')] p54: thpad.connectstyle=Relief thpad.reliefconductorwidth=10 thpad.reliefentries=4 thpad.polygonreliefangle="90 Angle" thpad.airgapwidth=10 smdpad.connectstyle=Direct smdpad.reliefconductorwidth=10 smdpad.reliefentries=4 smdpad.polygonreliefangle="90 Angle" smdpad.airgapwidth=10 via.connectstyle=Direct via.reliefconductorwidth=10 via.reliefentries=4 via.polygonreliefangle="90 Angle" via.airgapwidth=10
PolygonConnect PolygonConnect_32 [All vs IsNamedPolygon('NETC2_1_L01_P1604')] p55: thpad.connectstyle=Relief thpad.reliefconductorwidth=10 thpad.reliefentries=4 thpad.polygonreliefangle="90 Angle" thpad.airgapwidth=10 smdpad.connectstyle=Direct smdpad.reliefconductorwidth=10 smdpad.reliefentries=4 smdpad.polygonreliefangle="90 Angle" smdpad.airgapwidth=10 via.connectstyle=Direct via.reliefconductorwidth=10 via.reliefentries=4 via.polygonreliefangle="90 Angle" via.airgapwidth=10
PolygonConnect PolygonConnect_31 [All vs IsNamedPolygon('GND_L01_P1608')] p56: thpad.connectstyle=Relief thpad.reliefconductorwidth=10 thpad.reliefentries=4 thpad.polygonreliefangle="90 Angle" thpad.airgapwidth=10 smdpad.connectstyle=Direct smdpad.reliefconductorwidth=10 smdpad.reliefentries=4 smdpad.polygonreliefangle="90 Angle" smdpad.airgapwidth=10 via.connectstyle=Direct via.reliefconductorwidth=10 via.reliefentries=4 via.polygonreliefangle="90 Angle" via.airgapwidth=10
PolygonConnect PolygonConnect_30 [All vs IsNamedPolygon('VCC_DUT_L01_P1606')] p57: thpad.connectstyle=Relief thpad.reliefconductorwidth=10 thpad.reliefentries=4 thpad.polygonreliefangle="90 Angle" thpad.airgapwidth=10 smdpad.connectstyle=Direct smdpad.reliefconductorwidth=10 smdpad.reliefentries=4 smdpad.polygonreliefangle="90 Angle" smdpad.airgapwidth=10 via.connectstyle=Direct via.reliefconductorwidth=10 via.reliefentries=4 via.polygonreliefangle="90 Angle" via.airgapwidth=10
PolygonConnect PolygonConnect_29 [All vs IsNamedPolygon('GND_L01_P1614')] p58: thpad.connectstyle=Relief thpad.reliefconductorwidth=10 thpad.reliefentries=4 thpad.polygonreliefangle="90 Angle" thpad.airgapwidth=10 smdpad.connectstyle=Relief smdpad.reliefconductorwidth=10 smdpad.reliefentries=4 smdpad.polygonreliefangle="90 Angle" smdpad.airgapwidth=10 via.connectstyle=Direct via.reliefconductorwidth=10 via.reliefentries=4 via.polygonreliefangle="90 Angle" via.airgapwidth=10
PolygonConnect PolygonConnect_28 [All vs IsNamedPolygon('GND_L01_P2387')] p59: thpad.connectstyle=Relief thpad.reliefconductorwidth=10 thpad.reliefentries=4 thpad.polygonreliefangle="90 Angle" thpad.airgapwidth=10 smdpad.connectstyle=Direct smdpad.reliefconductorwidth=10 smdpad.reliefentries=4 smdpad.polygonreliefangle="90 Angle" smdpad.airgapwidth=10 via.connectstyle=Direct via.reliefconductorwidth=10 via.reliefentries=4 via.polygonreliefangle="90 Angle" via.airgapwidth=10
PolygonConnect PolygonConnect_27 [All vs IsNamedPolygon('GND_L01_P2387')] p60: thpad.connectstyle=Relief thpad.reliefconductorwidth=10 thpad.reliefentries=4 thpad.polygonreliefangle="90 Angle" thpad.airgapwidth=10 smdpad.connectstyle=Relief smdpad.reliefconductorwidth=10 smdpad.reliefentries=4 smdpad.polygonreliefangle="90 Angle" smdpad.airgapwidth=10 via.connectstyle=Direct via.reliefconductorwidth=10 via.reliefentries=4 via.polygonreliefangle="90 Angle" via.airgapwidth=10
PolygonConnect PolygonConnect_26 [All vs IsNamedPolygon('GND_L01_P2387')] p61: thpad.connectstyle=Relief thpad.reliefconductorwidth=10 thpad.reliefentries=4 thpad.polygonreliefangle="90 Angle" thpad.airgapwidth=10 smdpad.connectstyle=Direct smdpad.reliefconductorwidth=10 smdpad.reliefentries=4 smdpad.polygonreliefangle="90 Angle" smdpad.airgapwidth=10 via.connectstyle=Direct via.reliefconductorwidth=10 via.reliefentries=4 via.polygonreliefangle="90 Angle" via.airgapwidth=10
PolygonConnect PolygonConnect_25 [All vs IsNamedPolygon('SW0_L01_P466')] p62: thpad.connectstyle=Relief thpad.reliefconductorwidth=10 thpad.reliefentries=4 thpad.polygonreliefangle="90 Angle" thpad.airgapwidth=10 smdpad.connectstyle=Direct smdpad.reliefconductorwidth=10 smdpad.reliefentries=4 smdpad.polygonreliefangle="90 Angle" smdpad.airgapwidth=10 via.connectstyle=Direct via.reliefconductorwidth=10 via.reliefentries=4 via.polygonreliefangle="90 Angle" via.airgapwidth=10
PolygonConnect PolygonConnect_24 [All vs IsNamedPolygon('VIN1_L01_P1602')] p63: thpad.connectstyle=Relief thpad.reliefconductorwidth=10 thpad.reliefentries=4 thpad.polygonreliefangle="90 Angle" thpad.airgapwidth=10 smdpad.connectstyle=Direct smdpad.reliefconductorwidth=10 smdpad.reliefentries=4 smdpad.polygonreliefangle="90 Angle" smdpad.airgapwidth=10 via.connectstyle=Direct via.reliefconductorwidth=10 via.reliefentries=4 via.polygonreliefangle="90 Angle" via.airgapwidth=10
PolygonConnect PolygonConnect_23 [All vs IsNamedPolygon('CSSUM_L01_P1600')] p64: thpad.connectstyle=Direct thpad.reliefconductorwidth=10 thpad.reliefentries=4 thpad.polygonreliefangle="90 Angle" thpad.airgapwidth=10 smdpad.connectstyle=Relief smdpad.reliefconductorwidth=10 smdpad.reliefentries=4 smdpad.polygonreliefangle="90 Angle" smdpad.airgapwidth=10 via.connectstyle=Direct via.reliefconductorwidth=10 via.reliefentries=4 via.polygonreliefangle="90 Angle" via.airgapwidth=10
PolygonConnect PolygonConnect_22 [All vs IsNamedPolygon('CSSUM_L01_P1600')] p65: connectstyle=Relief reliefconductorwidth=10 reliefentries=4 polygonreliefangle="90 Angle" airgapwidth=10
PolygonConnect PolygonConnect_21 [All vs IsNamedPolygon('Top Layer-Vin1')] p66: connectstyle=Direct reliefconductorwidth=10 reliefentries=4 polygonreliefangle="90 Angle" airgapwidth=10
PolygonConnect PolygonConnect_20 [All vs IsNamedPolygon('Top Layer-Vin1')] p67: connectstyle=Direct reliefconductorwidth=10 reliefentries=4 polygonreliefangle="90 Angle" airgapwidth=10
PolygonConnect PolygonConnect_19 [All vs IsNamedPolygon('TOP-SW8')] p68: connectstyle=Direct reliefconductorwidth=10 reliefentries=4 polygonreliefangle="90 Angle" airgapwidth=10
PolygonConnect PolygonConnect_18 [All vs IsNamedPolygon('TOP-VOU8')] p69: connectstyle=Direct reliefconductorwidth=10 reliefentries=4 polygonreliefangle="90 Angle" airgapwidth=10
PolygonConnect PolygonConnect_17 [All vs IsNamedPolygon('Top Layer-Vin1')] p70: connectstyle=Direct reliefconductorwidth=10 reliefentries=4 polygonreliefangle="90 Angle" airgapwidth=10
PolygonConnect PolygonConnect_16 [All vs IsNamedPolygon('Top Layer-GND')] p71: connectstyle=Direct reliefconductorwidth=10 reliefentries=4 polygonreliefangle="90 Angle" airgapwidth=10
PolygonConnect PolygonConnect_15 [All vs IsNamedPolygon('Top Layer-GND')] p72: connectstyle=Direct reliefconductorwidth=10 reliefentries=4 polygonreliefangle="90 Angle" airgapwidth=10
PolygonConnect PolygonConnect_14 [All vs IsNamedPolygon('Top Layer-Vin1')] p73: connectstyle=Direct reliefconductorwidth=10 reliefentries=4 polygonreliefangle="90 Angle" airgapwidth=10
PolygonConnect PolygonConnect_13 [All vs IsNamedPolygon('TOP-VOU8')] p74: connectstyle=Direct reliefconductorwidth=10 reliefentries=4 polygonreliefangle="90 Angle" airgapwidth=10
PolygonConnect PolygonConnect_12 [All vs IsNamedPolygon('TOP-SW8')] p75: connectstyle=Direct reliefconductorwidth=10 reliefentries=4 polygonreliefangle="90 Angle" airgapwidth=10
PolygonConnect PolygonConnect_11 [All vs IsNamedPolygon('BOTTOM-GND')] p76: connectstyle=Direct reliefconductorwidth=10 reliefentries=4 polygonreliefangle="90 Angle" airgapwidth=10
PolygonConnect PolygonConnect_10 [All vs IsNamedPolygon('BOTTOM-GND 1')] p77: connectstyle=Direct reliefconductorwidth=10 reliefentries=4 polygonreliefangle="90 Angle" airgapwidth=10
PolygonConnect PolygonConnect_9 [All vs IsNamedPolygon('BOTTOM-N28887058')] p78: connectstyle=Direct reliefconductorwidth=10 reliefentries=4 polygonreliefangle="90 Angle" airgapwidth=10
PolygonConnect PolygonConnect_8 [All vs IsNamedPolygon('BOTTOM-N28887226')] p79: connectstyle=Direct reliefconductorwidth=10 reliefentries=4 polygonreliefangle="90 Angle" airgapwidth=10
PolygonConnect PolygonConnect_7 [All vs IsNamedPolygon('BOTTOM-AGND 16')] p80: connectstyle=Direct reliefconductorwidth=10 reliefentries=4 polygonreliefangle="90 Angle" airgapwidth=10
PolygonConnect PolygonConnect_6 [All vs IsNamedPolygon('VIN1_L06_P1534')] p81: connectstyle=Direct reliefconductorwidth=10 reliefentries=4 polygonreliefangle="90 Angle" airgapwidth=10
PolygonConnect PolygonConnect_5 [All vs IsNamedPolygon('BOTTOM-AGND 8')] p82: connectstyle=Direct reliefconductorwidth=10 reliefentries=4 polygonreliefangle="90 Angle" airgapwidth=10
PolygonConnect PolygonConnect_4 [All vs IsNamedPolygon('TOP-VOU8')] p83: connectstyle=Direct reliefconductorwidth=10 reliefentries=4 polygonreliefangle="90 Angle" airgapwidth=10
PolygonConnect PolygonConnect_3 [All vs IsNamedPolygon('TOP-SW8')] p84: connectstyle=Direct reliefconductorwidth=10 reliefentries=4 polygonreliefangle="90 Angle" airgapwidth=10
PolygonConnect PolygonConnect_2 [All vs IsNamedPolygon('TOP-N28860843')] p85: connectstyle=Direct reliefconductorwidth=10 reliefentries=4 polygonreliefangle="90 Angle" airgapwidth=10
PolygonConnect PolygonConnect_1 [All vs IsNamedPolygon('Top Layer-Vin1')] p86: connectstyle=Direct reliefconductorwidth=10 reliefentries=4 polygonreliefangle="90 Angle" airgapwidth=10
PolygonConnect [All vs IsNamedPolygon('Top Layer-GND')] p87: connectstyle=Direct reliefconductorwidth=10 reliefentries=4 polygonreliefangle="90 Angle" airgapwidth=10
PolygonConnect "Top Layer Polygons" [(InPolygon AND OnLayer('top Layer'))] p88: connectstyle=Direct reliefconductorwidth=10 reliefentries=4 polygonreliefangle="90 Angle" airgapwidth=10
PolygonConnect MOD_1x1_36 [All vs (OnLayer('Top Layer') AND HasFootprint('MOD_1x1_36'))] p89: thpad.connectstyle=Direct thpad.reliefconductorwidth=10 thpad.reliefentries=4 thpad.polygonreliefangle="90 Angle" thpad.airgapwidth=10 smdpad.connectstyle=Relief smdpad.reliefconductorwidth=10 smdpad.reliefentries=4 smdpad.polygonreliefangle="90 Angle" smdpad.airgapwidth=10 via.connectstyle=Direct via.reliefconductorwidth=10 via.reliefentries=4 via.polygonreliefangle="90 Angle" via.airgapwidth=10
PolygonConnect "Top Layer Vbat" [All vs IsNamedPolygon('Top Layer-Vbat')] p90: connectstyle=Direct reliefconductorwidth=10 reliefentries=4 polygonreliefangle="90 Angle" airgapwidth=10
PolygonConnect "Top Layer Vbat GND" [All vs IsNamedPolygon('GND_L03_P1716')] p91: connectstyle=Direct reliefconductorwidth=10 reliefentries=4 polygonreliefangle="90 Angle" airgapwidth=10
PolygonConnect "Top Layer Vbat RB" [All vs IsNamedPolygon('Top Layer-Vbat_RB')] p92: connectstyle=Direct reliefconductorwidth=10 reliefentries=4 polygonreliefangle="90 Angle" airgapwidth=10
RoomDefinition "OUTPUT MEASUREMENTS" [InComponentClass('OUTPUT MEASUREMENTS')] p1: confinementstyle=ConfineIn formatcopy=TRUE lockcomponents=FALSE outline 0,0 5000,0 5000,4000 0,4000
RoomDefinition "INPUT MEASUREMENTS" [InComponentClass('INPUT MEASUREMENTS')] p2: confinementstyle=ConfineIn formatcopy=TRUE lockcomponents=FALSE outline 0,0 5000,0 5000,4000 0,4000
RoomDefinition STRATA [InComponentClass('STRATA')] p3: confinementstyle=ConfineIn formatcopy=TRUE lockcomponents=FALSE outline 0,0 5000,0 5000,4000 0,4000
RoomDefinition "PCB MODULES" [InComponentClass('PCB MODULES')] p4: confinementstyle=ConfineIn formatcopy=TRUE lockcomponents=FALSE outline 0,0 5000,0 5000,4000 0,4000
RoutingCorners [All] p1: cornerstyle=45-Degree minsetback=50 maxsetback=50
RoutingVias [All] p1: holewidth=11.81 width=23.62 viastyle="Through Hole" minholewidth=8 minwidth=16 maxholewidth=200 maxwidth=400
SilkToSilkClearance [All] p1: silktosilkclearance=0
SilkToSolderMaskClearance SilkToSolderMaskClearance_text [Locked and IsText] p1: minsilkscreentomaskgap=0 clearancetoexposedcopper=TRUE
SilkToSolderMaskClearance [IsPad] p2: minsilkscreentomaskgap=0 clearancetoexposedcopper=TRUE
SolderMaskExpansion [All] p1: expansion=1.57
Width [All] p1: maxlimit=60 minlimit=8 preferedwidth=10 minimp=50.000000 maximp=50.000000 favimp=50.000000
22 further rules are at their usual default settings.

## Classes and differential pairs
component class "OUTPUT MEASUREMENTS": Cfl Cfo CL Cout Cso Doi Dov DpzL GND_out J6 J9 Jout "LOAD TRANSIENT" QL RdG ReuG Rload1 Rload2 Rload3 Rol Ron Rop Rou Rout Rpdlt1 Rpdlt2 RtrG UIout Vout
component class "PCB MODULES": EN EN/IO2 IO0 IO1 IO2 IO3 J5 J7 J10 J11 J12 J13 J14 J15 J16 J17 PG PG/IO3 Rpd0 Rpd1 Rpd2 Rpd3 RpdEN RpdPG Rpds Rpus Rscl Rsda SYNC U1 U2 U3 Vaux
component class "INPUT MEASUREMENTS": Cen Cfi Cgsp Cin Csi Dii Div Dpz Dz GND_in J4 J8 Jin Qen Qenpmos Qrp Ren1 Ren2 Rgsp Ril Rim Rin Rip Riu UIin Vin
component class STRATA: Cin1 Cin2 Cout1 Cout2 Csmem Cstmp JStrata Rtmp Uee Us Utmp

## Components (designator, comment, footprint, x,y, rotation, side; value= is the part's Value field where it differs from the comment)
Cen "10n 50V 0603" CAPC1608X90X40ML10T20 684.08,1345.29 r180 bottom
Cfi "GCJ188R71H103KA01D" 0603_CAP 1000,1550 r180 bottom value=10n
Cfl "GCJ188R71H104KA12D" 0603_CAP_MAX 4840,2000 r90 bottom value=0.1u
Cfo "GCJ188R71H103KA01D" 0603_CAP 4000,1550 r180 bottom value=10n
Cgsp "10n 50V 0603" CAPC1608X90X40ML10T20 331.22,1606.54 r270 bottom
Cin "100uF 63 V" Elyt_Radial_10X12.5 650,2000 r90 top value=100u
Cin1 "GRT31CR71E106KE13" 1206_CAP 925,863.98 r270 bottom value=10u
Cin2 "GCM21BR71H105KA03L" 0805_CAP_MAX 823.48,833.46 r270 bottom value=1u
CL "Current Loop for 2.5 sqmm Cu wire" Current_Loop_2.5sqmm 4435,2392.4 r270 bottom value=0.005
Cout "EEUFR1J101B" Elyt_Radial_10X12.5 4350,2000 r90 top value=100u
Cout1 "GCM31CR71A226KE02L" 1206_CAP_MAX 925,675 r90 bottom value=22u
Cout2 "GCM21BR71C475KA73L" 0805_CAP_MAX 825,700 r90 bottom value=4.7u
Csi "GCJ188R71H104KA12D" 0603_CAP 1000,1345 r0 bottom value=0.1u
Csmem "GCM21BR71H105KA03L" 0805_CAP_MAX 3115,320 r0 bottom value=1u
Cso "GCJ188R71H104KA12D" 0603_CAP 4000,1345 r0 bottom value=0.1u
Cstmp "GCM21BR71H105KA03L" 0805_CAP_MAX 3115,445 r180 bottom value=1u
Dii "MMSZ5225BT1G" SOD-123 2605,650 r90 bottom
Div "MMSZ5225BT1G" SOD-123 2705,650 r90 bottom
Doi "MMSZ5225BT1G" SOD-123 2923.65,646.54 r90 bottom
Dov "MMSZ5225BT1G" SOD-123 2805,650 r90 bottom
Dpz "4.7V 0.5W" ONSC-SOD-123-2-425-04_V 454.37,1579.18 r180 bottom
DpzL "6V2 225mW" ONSC-SOT-23-3-318-08_V 4522.94,2642.6 r180 bottom
Dz "36V 3W" ONSC-SMB-2-403A-03_H_V 385,1899.24 r90 bottom
EN "22-28-4360" Header_3 1200,500 r270 top value="3 POS"
EN/IO2 "22-28-4360" Header_3 1675,500 r270 top value="3 POS"
GND_in "571-0100-01" "PCB Jack 4mm - black" 385.83,3000 r270 top value=Black
GND_out "571-0100-01" "PCB Jack 4mm - black" 4559.26,3000 r90 top value=Black
IO0 "22-28-4360" Header_3 800,500 r270 top value="3 POS"
IO1 "22-28-4360" Header_3 1000,500 r270 top value="3 POS"
IO2 "22-28-4360" Header_3 1400,500 r270 top value="3 POS"
IO3 "22-28-4360" Header_3 3600,500 r270 top value="3 POS"
J4 "160-1026-02-01-00" "Terminal Turret" 100,2500 r0 top
J5 "160-1026-02-01-00" "Terminal Turret" 500,125.79 r0 top
J6 "160-1026-02-01-00" "Terminal Turret" 4860.44,2498.06 r0 top
J7 "160-1026-02-01-00" "Terminal Turret" 4475,122.07 r0 top
J8 "5010" TestPoint_1.6mm 100,1500 r0 top
J9 "5010" TestPoint_1.6mm 4832.62,1500 r0 top
J10 "5010" TestPoint_1.6mm 800,100 r0 top
J11 "5010" TestPoint_1.6mm 1200,100 r0 top
J12 "5010" TestPoint_1.6mm 1000,100 r0 top
J13 "5010" TestPoint_1.6mm 1400,100 r0 top
J14 "5010" TestPoint_1.6mm 4000,100 r0 top
J15 "5010" TestPoint_1.6mm 3600,100 r0 top
J16 "5010" TestPoint_1.6mm 4200,100 r0 top
J17 "5010" TestPoint_1.6mm 3800,100 r0 top
Jin "ED120/2S" ED120/2DS 2.48,1800.01 r0 top value=TSW-102-07-G-S
Jout "ED120/2S" ED120/2DS 4997.52,2200 r180 top value=TSW-102-07-G-S
JStrata "613016243121" 613016243121_Strata 2500,179.13 r0 top
"LOAD TRANSIENT" "SMB_STR_TH_50OHM" SMB_STR_TH 4850,3450 r90 top value=1-1337482-0
PG "22-28-4360" Header_3 3800,500 r270 top value="3 POS"
PG/IO3 "22-28-4360" Header_3 3364.84,500 r270 top value="3 POS"
Qen "BC546BTF" ONSC-TO-92-3-29-11 747.97,1235 r0 bottom
Qenpmos "ATP108-TL-H" ONSC-ATPAK-3-369AM_V 683.15,1718.83 r90 bottom
QL "NTMFS4C302NT1G" ONSC-DFN-5-488AA_V 4225,2482.99 r270 bottom (schematic designator Q1)
Qrp "ATP108-TL-H" ONSC-ATPAK-3-369AM_V 432.28,1235 r270 bottom
RdG "100k 0603" RESC1608X55X25ML10T15 4590,3134.72 r90 bottom
Ren1 "4k7 0603" RESC1608X55X25LL10T15 684.19,1390 r0 bottom
Ren2 "10k 0603" RESC1608X55X25ML10T15 795.92,1088.98 r90 bottom
ReuG "1K2 0603" RESC1608X55X25LL10T15 4706.38,3105 r0 bottom
Rgsp "10K 1206" FP-RC3216-IPC_B 250,1553.46 r90 bottom
Ril "MCT0603MD1001DP500" 0603_RES 1086.41,1520 r270 bottom value=1k
Rim "RC0603FR-074R7L" 0603_RES 1030,1640 r270 bottom value=4R7
Rin "PE2512DKM7W0R01L" 2512_RES 1000,1800 r0 bottom value=0.010R
Rip "RC0603FR-074R7L" 0603_RES 970,1640 r270 bottom value=4R7
Riu "RQ73C1J5K62BTD" 0603_RES 1086.41,1640 r270 bottom value=5.62k
Rload1 "3R3 1W 2512" RESC2512(6432)_N 4700.6,2118.5 r270 bottom value="3.30 Ohm"
Rload2 "3R3 1W 2512" RESC2512(6432)_N 4550.59,2118.5 r270 bottom value="3.30 Ohm"
Rload3 "3R3 1W 2512" RESC2512(6432)_N 4185.24,2118.5 r270 bottom value="3.30 Ohm"
Rol "MCT0603MD1001DP500" 0603_RES 3901.43,1518.68 r270 bottom value=1k
Ron "RC0603FR-074R7L" 0603_RES 4030,1640 r270 bottom value=4R7
Rop "RC0603FR-074R7L" 0603_RES 3970,1640 r270 bottom value=4R7
Rou "RQ73C1J5K62BTD" 0603_RES 3900,1640 r270 bottom value=5.62k
Rout "PE2512DKM7W0R01L" 2512_RES 4000,1800 r0 bottom value=0.010R
Rpd0 "RC0603FR-0710KL" 0603_RES 900,325 r270 bottom value=10k
Rpd1 "RC0603FR-0710KL" 0603_RES 1100,325 r270 bottom value=10k
Rpd2 "RC0603FR-0710KL" 0603_RES 1500,325 r270 bottom value=10k
Rpd3 "RC0603FR-0710KL" 0603_RES 3700,325 r270 bottom value=10k
RpdEN "RC0603FR-0710KL" 0603_RES 1300,325 r270 bottom value=10k
Rpdlt1 "50R 0603" RESC1609X50X30NL10T20 4705.39,3180 r180 bottom
Rpdlt2 "50R 0603" RESC1609X50X30NL10T20 4855,3204.61 r90 bottom
RpdPG "RC0603FR-0710KL" 0603_RES 3900,325 r270 bottom value=10k
Rpds "RC0603FR-0751RL" 0603_RES 400,516.54 r270 bottom value=51
Rpus "Short" 0603_RES 525,516.54 r90 bottom value=0R
Rscl "RC0603FR-0710KL" 0603_RES 2750.92,166.22 r90 bottom value=10k
Rsda "RC0603FR-0710KL" 0603_RES 2650.92,166.22 r90 bottom value=10k
Rtmp "RC0603FR-0710KL" 0603_RES 3060.86,750 r180 bottom value=10k
RtrG "220R 0603" RESC1608X55X25ML10T15 4399.27,2588.71 r90 bottom
SYNC "SMB_STR_TH_50OHM" SMB_STR_TH 150,550 r90 top value=1-1337482-0
U1 "MOD_0.5x0.5_16" MOD_0.5x0.5_16 2500,2000 r0 top
U2 "MOD_1x1_36" MOD_1x1_36 2500,2000 r0 top
U3 "MOD_2x2_76" MOD_2x2_76 2500,2000 r0 top
Uee "CAT24C512" SOIC-8 3115,170 r180 bottom value=CAT24C512WI-GT3
UIin "NCS213R" SC-88/SC70-6/SOT-363 1013,1449 r90 bottom value=NCV213RSQT2G
UIout "NCS213R" SC-88/SC70-6/SOT-363 4012.5,1449 r90 bottom value=NCV213RSQT2G
Us "NCV8664CDT50" DPAK-3_L 536.61,790.16 r180 bottom value=NCV8664CDT50RKG
Utmp "NCT375" SOIC-8 3115,595 r0 bottom value=NCT375DR2G
Vaux "22-28-4360" Header_3 1925,500 r270 top value="3 POS"
Vin "571-0500-01" "PCB Jack 4mm - red" 385.83,1000 r270 top value=Red
Vout "571-0500-01" "PCB Jack 4mm - red" 4558.82,1000 r90 top value=Red

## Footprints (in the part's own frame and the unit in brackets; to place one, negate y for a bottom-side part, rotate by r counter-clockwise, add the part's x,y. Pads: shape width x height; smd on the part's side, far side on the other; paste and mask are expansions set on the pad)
0603_CAP [mm] "0603, MLCC, GRT Series, middle dimensions from reflow soldering, +/-0.15/+/-0.20 tolerances"
  rect 0.75x0.9 smd: 1(-0.775,0) 2(0.775,0)
  body extent -0.85,-0.45 0.85,0.45, height 0.9
0603_CAP_MAX [mm] "0603, MLCC, GCM Series, max dimensions from reflow soldering"
  rect 0.8x1 smd: 1(-0.85,0) 2(0.85,0)
  body extent -0.85,-0.45 0.85,0.45, height 0.9
0603_RES [mm] "Chip Resistor, 2-Leads, Body 1.60x0.80mm, IPC Medium Density"
  rect 0.9x0.8 smd: 1(-0.85,0) 2(0.85,0)
  body extent -0.85,-0.45 0.85,0.45, height 0.55
0805_CAP_MAX [mm] "0805, MLCC, GCM Series, max dimensions from reflow soldering"
  rect 0.8x1.4 smd: 1(-1.1,0) 2(1.1,0)
  body extent -1.07,-0.7 1.08,0.7, height 1.4
1206_CAP [mm] "1206_CAP, MLCC, GRT Series, middle dimensions from reflow soldering, +/-0.20 tolerances"
  rect 1.05x1.6 smd: 1(-1.475,0) 2(1.475,0)
  silkscreen extent -0.3,-0.7 0.3,0.7, body extent -1.7,-0.9 1.7,0.9, height 1.8
1206_CAP_MAX [mm] "1206, MLCC, GCM Series, max dimensions from reflow soldering"
  rect 1.3x1.9 smd: 1(-1.7,0) 2(1.7,0)
  silkscreen extent -0.3,-0.85 0.3,0.85, body extent -1.7,-0.9 1.7,0.9, height 1.8
2512_RES [mm] "2512, Reflow, YAGEO"
  rect 1.3x4.1 smd: 1(-3.048,0) 2(3.048,0)
  silkscreen extent -3.96,-2.31 3.96,2.31, body extent -3.17,-1.5 3.17,1.5, height 1.6
613016243121_Strata [mm] "Socket Header, Pitch 2.54 mm, THT, Angled, dual row, 16p"
  rect 1.5x1.5 hole 1.02: 1(-8.89,8.15)
  round 1.5 hole 1.02: 2(-8.89,5.61) 3(-6.35,8.15) 4(-6.35,5.61) 5(-3.81,8.15) 6(-3.81,5.61) 7(-1.27,8.15) 8(-1.27,5.61) 9(1.27,8.15) 10(1.27,5.61) 11(3.81,8.15) 12(3.81,5.61) 13(6.35,8.15) 14(6.35,5.61) 15(8.89,8.15) 16(8.89,5.61)
  silkscreen extent -10.56,-4.35 10.56,4.35, body extent -10.41,-4.25 10.41,8.35, height 5.05
CAPC1608X90X40ML10T20 [mm] "Chip Capacitor, 2-Leads, Body 1.7x0.9mm, IPC Low Density"
  rect 1.05x1.05 smd: 1(-0.675,0) 2(0.675,0)
  body extent -0.85,-0.45 0.85,0.45, height 0.9
Current_Loop_2.5sqmm [mm]
  round 3.9 / inner round 2.9 / far side round 3.9 hole 1.9: 1(0,0) 2(20,0)
  silkscreen extent 2.75,0 17.25,0
DPAK-3_L [mm] "D-PAK, 3-Pads, Body 8.31x6.73mm (max), IPC Low Density"
  rect 3.3x1.05 smd: 1(-4.15,2.29) 2(-4.15,-2.29)
  rect 6.2x5.55 smd: 3(2.65,0)
  silkscreen extent -4.28,-3.35 -0.85,3.49, body extent -4.95,-3.37 5.15,3.37, height 2.37
ED120/2DS [mm] "Large Screw Terminal"
  rrect5% 2x2 hole 1.25: 1(3.937,7.62)
  round 2 hole 1.25: 2(3.937,2.54)
  silkscreen extent -0.06,-0.04 8.94,10.68, body extent -0.06,0 8.94,10.86, height 13
Elyt_Radial_10X12.5 [mm] "Electrolytic Radial Aluminium capacitor 10 x 12.5 mm"
  rect 1.4x1.4 hole 0.7: 1(-2.54,0)
  round 1.4 hole 0.7: 2(2.54,0)
  silkscreen extent -5,-5 5,5, body extent -5.25,-5.25 5.25,5.25, height 14
FP-RC3216-IPC_B [mil]
  rect 45.47x69.22 smd paste+0 mask+0: 1(-58.1,0) 2(58.1,0)
  silkscreen extent -24,-35 24,35, body extent -63,-31 63,31, height 26
Header_3 [mm]
  rect 1.6x1.6 hole 1: 1(0,0)
  round 1.6 hole 1: 2(2.54,0) 3(5.08,0)
  silkscreen extent -1.14,-1.14 6.22,1.14, body extent -1.27,-1.24 6.35,1.25, height 8.54
MOD_0.5x0.5_16 [mil]
  rect 100x80 smd: 1(-250,150) 2(-250,50) 3(-250,-50) 4(-250,-150) 9(250,-150) 10(250,-50) 11(250,50) 12(250,150)
  rect 80x100 smd: 5(-150,-250) 6(-50,-250) 7(50,-250) 8(150,-250) 13(150,250) 14(50,250) 15(-50,250) 16(-150,250)
  silkscreen extent -295,-295 295,295
MOD_1x1_36 [mil]
  rect 100x80 smd: 1(-500,400) 2(-500,300) 3(-500,200) 4(-500,100) 5(-500,0) 6(-500,-100) 7(-500,-200) 8(-500,-300) 9(-500,-400) 19(500,-400) 20(500,-300) 21(500,-200) 22(500,-100) 23(500,0) 24(500,100) 25(500,200) 26(500,300) 27(500,400)
  rect 80x100 smd: 10(-400,-500) 11(-300,-500) 12(-200,-500) 13(-100,-500) 14(0,-500) 15(100,-500) 16(200,-500) 17(300,-500) 18(400,-500) 28(400,500) 29(300,500) 30(200,500) 31(100,500) 32(0,500) 33(-100,500) 34(-200,500) 35(-300,500) 36(-400,500)
  silkscreen extent -545,-545 545,545
MOD_2x2_76 [mil]
  rect 100x80 smd: 1(-1000,900) 2(-1000,800) 3(-1000,700) 4(-1000,600) 5(-1000,500) 6(-1000,400) 7(-1000,300) 8(-1000,200) 9(-1000,100) 10(-1000,0) 11(-1000,-100) 12(-1000,-200) 13(-1000,-300) 14(-1000,-400) 15(-1000,-500) 16(-1000,-600) 17(-1000,-700) 18(-1000,-800) 19(-1000,-900) 39(1000,-900) 40(1000,-800) 41(1000,-700) 42(1000,-600) 43(1000,-500) 44(1000,-400) 45(1000,-300) 46(1000,-200) 47(1000,-100) 48(1000,0) 49(1000,100) 50(1000,200) 51(1000,300) 52(1000,400) 53(1000,500) 54(1000,600) 55(1000,700) 56(1000,800) 57(1000,900)
  rect 80x100 smd: 20(-900,-1000) 21(-800,-1000) 22(-700,-1000) 23(-600,-1000) 24(-500,-1000) 25(-400,-1000) 26(-300,-1000) 27(-200,-1000) 28(-100,-1000) 29(0,-1000) 30(100,-1000) 31(200,-1000) 32(300,-1000) 33(400,-1000) 34(500,-1000) 35(600,-1000) 36(700,-1000) 37(800,-1000) 38(900,-1000) 58(900,1000) 59(800,1000) 60(700,1000) 61(600,1000) 62(500,1000) 63(400,1000) 64(300,1000) 65(200,1000) 66(100,1000) 67(0,1000) 68(-100,1000) 69(-200,1000) 70(-300,1000) 71(-400,1000) 72(-500,1000) 73(-600,1000) 74(-700,1000) 75(-800,1000) 76(-900,1000)
  silkscreen extent -1045,-1045 1045,1045
ONSC-ATPAK-3-369AM_V [mm] "DPAK, 3-Leads, Body 7.3x6.5mm, Pitch 2.3mm"
  rect 1.6x1.5 smd: 1(-6.15,2.3) 3(-6.15,-2.3)
  rect 6.7x6.5 smd: 4(0,0)
  silkscreen extent -7.62,-3.25 -3.75,3.25, body extent -4.45,-3.25 2.85,3.25, height 1.77
ONSC-DFN-5-488AA_V [mm] "DFN, 5-Leads, Body 5.9x4.9mm, Pitch 1.27mm"
  rect 1x0.75 smd: 1(-2.795,1.905) 2(-2.795,0.635) 3(-2.795,-0.635) 4(-2.795,-1.905)
  rect 1x0.75 smd paste+0 mask+0: 5(0,0)
  Top Layer region: -0.905,-2.775 -0.905,-2.28 -1.33,-2.28 -1.33,2.28 -0.905,2.28 -0.905,2.775 0,2.775 0,2.28 3.2,2.28 3.2,1.53 2.725,1.53 2.725,-1.53 3.2,-1.53 3.2,-2.28 0,-2.28 0,-2.775
  silkscreen extent -3.97,1.78 -3.72,2.03, body extent -2.95,-2.45 2.95,2.45, height 1.1
ONSC-SMB-2-403A-03_H_V [mil] "Molded, 2-Leads, Body 4.6x3.95mm"
  rect 85x107.99 smd: 1(-87.01,0) 2(87.01,0)
  silkscreen extent -125,-79 91,81, body extent -91,-78 91,78, height 95
ONSC-SOD-123-2-425-04_V [mm] "SOD, 2-Leads, Body 2.69x1.6mm"
  rect 0.91x1.22 smd: 1(-1.635,0) 2(1.635,0)
  silkscreen extent -1.76,-0.8 0.78,1.28, body extent -1.35,-0.8 1.35,0.8, height 1.35
ONSC-SOT-23-3-318-08_V [mm] "SOT23, 3-Leads, Body 2.92x1.3mm, Pitch 0.95mm"
  rect 0.9x0.8 smd: 1(-1,0.95) 2(-1,-0.95) 3(1,0)
  silkscreen extent -1.13,-1.46 0.65,2.02, body extent -0.65,-1.46 0.65,1.46, height 1.11
ONSC-TO-92-3-29-11 [mm] "TO, 3-Leads, Body Dia 4.7mm, Pitch 1.27mm"
  rect 1.05x1.05 hole 0.8: 1(-1.27,0)
  round 1.05 hole 0.8: 2(0,0) 3(1.27,0)
  silkscreen extent -3.07,-1.34 2.35,2.35, body extent -2.35,-1.33 2.36,2.36, height 7.87
"PCB Jack 4mm - black" [mm] "DELTRON 571-0100-01"
  round 3.6 hole 1.8: 1(0,7.65) 1(0,-7.65)
  silkscreen extent -5,-10.45 5,10.5, body extent -4.9,-12.95 4.9,10.45, height 12.4
"PCB Jack 4mm - red" [mm] "DELTRON 571-0500-01"
  round 3.6 hole 1.8: 1(0,7.65) 1(0,-7.65)
  silkscreen extent -5,-10.45 5,10.5, body extent -4.9,-12.95 4.9,10.45, height 12.4
RESC1608X55X25LL10T15 [mm] "Chip Resistor, 2-Leads, Body 1.60x0.80mm, IPC High Density"
  rect 0.6x0.8 smd: 1(-0.65,0) 2(0.65,0)
  body extent -0.85,-0.45 0.85,0.45, height 0.55
RESC1608X55X25ML10T15 [mm] "Chip Resistor, 2-Leads, Body 1.60x0.80mm, IPC Low Density"
  rect 0.8x1 smd: 1(-0.75,0) 2(0.75,0)
  body extent -0.85,-0.45 0.85,0.45, height 0.55
RESC1609X50X30NL10T20 [mm] "Chip Resistor, 2-Leads, Body 1.55x0.85mm, IPC Medium Density"
  rect 0.8x0.95 smd: 1(-0.625,0) 2(0.625,0)
  body extent -0.82,-0.48 0.82,0.48, height 0.5
RESC2512(6432)_N [mm] "Chip Resistor, Body 6.4x3.2mm, IPC Medium Density"
  rect 1.25x3.35 smd: 1(-3,0) 2(3,0)
  silkscreen extent -2,-1.57 2,1.58, body extent -3.25,-1.7 3.25,1.7, height 0.75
